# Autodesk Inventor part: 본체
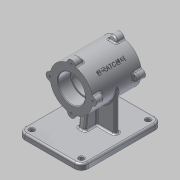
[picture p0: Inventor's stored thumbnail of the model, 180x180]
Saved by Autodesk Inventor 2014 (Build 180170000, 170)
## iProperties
Created: 2015-12
Part Number: 본체
Material: 알루미늄 6061
Document SubType Name: Modeling
Designer: L10
Density: 2.71 g/cm^3
Appearance: 알루미늄 - 평지
Mass: 1154.84 g
Surface Area: 823.447 cm^2
Volume: 426.142 cm^3
Author: L10
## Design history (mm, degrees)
sketch "스케치1"
  geometry: C1 r 37 at (0, 0); 1 further point
  constraints: 1 centre point, 1 coincident
  dimensions: "d0" = 74 diameter of C1
extrude "돌출1" new body sketch "스케치1" stored distance "d1" = 85; taper "d2" = 0 deg
sketch "스케치2"
  geometry: L1 (-42.5, -37)-(-42.5, 37) reference; L2 (-42.5, 37)-(42.5, 37) reference; L3 (42.5, 37)-(42.5, -37) reference; L4 (42.5, -37)-(-42.5, -37) reference; L5 (-42.5, 0)-(-20.5, 0); L6 (-20.5, 0)-(-20.5, 23.5); L7 (-20.5, 23.5)-(-42.5, 23.5); L8 (-42.5, 23.5)-(-42.5, 0); L9 (-20.5, 0)-(20.5, 0); L10 (20.5, 0)-(20.5, 21); L11 (20.5, 21)-(-20.5, 21); L12 (-20.5, 21)-(-20.5, 0); L13 (20.5, 0)-(42.5, 0); L14 (42.5, 0)-(42.5, 23.5); L15 (42.5, 23.5)-(20.5, 23.5); L16 (20.5, 23.5)-(20.5, 0); 2 further points
  constraints: 24 end point, 6 parallel, 3 horizontal, 3 perpendicular, 2 collinear, 1 coincident, 1 midpoint
  dimensions: "d3" = 47 diameter of L7 L9; "d4" = 42 diameter of L11 L9; "d5" = 22 distance of L6.end L7.end; "d6" = 41 distance of L10.end L11.end; "d7" = 85 distance between parallel lines of L14 L8 (derived)
revolve "회전1" sketch "스케치2" stored, may be unused: angle "d8" = 90 deg
node "작업 평면1"
sketch "스케치4"
  geometry: L1 (55, 60)-(-55, 60); L2 (-55, 60)-(-55, -80); L3 (-55, -80)-(55, -80); L4 (55, -80)-(55, 60); L5 (-37, -42.5)-(37, -42.5) reference; 4 further points
  constraints: 8 end point, 2 parallel, 1 horizontal, 1 midpoint, 1 perpendicular, 1 vertical alignment
  dimensions: "d13" = 140 distance of L3.end L1.start; "d14" = 110 distance of L1.start L1.end; "d15" = 37.5 distance between parallel lines of L5 L3
extrude "돌출3" join sketch "스케치4" distance "d16" = 10; taper "d17" = 0 deg
fillet "모깎기1" dims "d18" = 12
hole "구멍1" diameter "d21" = 8; stored, may be unused: countersink angle "d25" = 90 deg, drill point angle "d27" = 118 deg; dims "d19" = 10, "d20" = 10, "d22" = 6, "d23" = 4, "d24" = 2, "d26" = 8
hole "구멍2" diameter "d30" = 8; stored, may be unused: countersink angle "d34" = 90 deg, drill point angle "d36" = 118 deg; dims "d28" = 10, "d29" = 10, "d31" = 6, "d32" = 4, "d33" = 2, "d35" = 8
hole "구멍3" diameter "d39" = 8; stored, may be unused: countersink angle "d43" = 90 deg, drill point angle "d45" = 118 deg; dims "d37" = 10, "d38" = 10, "d40" = 6, "d41" = 4, "d42" = 2, "d44" = 8
hole "구멍4" diameter "d48" = 8; stored, may be unused: countersink angle "d52" = 90 deg, drill point angle "d54" = 118 deg; dims "d46" = 10, "d47" = 10, "d49" = 6, "d50" = 4, "d51" = 2, "d53" = 8
sketch "스케치6"
  geometry: L1 (-55, 48)-(-55, -68) reference; L2 (-43, -80)-(43, -80) reference; L3 (-6, -25)-(6, -25); L4 (6, -25)-(6, 25); L5 (6, 25)-(-6, 25); L6 (-6, 25)-(-6, -25); L7 (-37, -4)-(37, -4); L8 (37, -4)-(37, 4); L9 (37, 4)-(-37, 4); L10 (-37, 4)-(-37, -4); 3 further points
  constraints: 16 end point, 4 parallel, 2 horizontal, 2 midpoint, 2 perpendicular, 1 horizontal alignment, 1 vertical alignment
  dimensions: "d59" = 12 distance of L4.end L5.end; "d60" = 8 distance of L9.end L7.start; "d61" = 76 distance between parallel lines of L2 L7; "d62" = 49 distance between parallel lines of L1 L6; "d63" = 50 distance of L3.end L4.end; "d64" = 74 distance of L8.end L9.end
extrude "돌출4" join sketch "스케치6" stored distance "d65" = 10; taper "d66" = 0 deg
fillet "모깎기2" dims "d67" = 3
chamfer "모따기1" distance "d71" = 1; stored, may be unused: second distance "d72" = 2, angle "d73" = 20 deg
chamfer "모따기2" distance "d74" = 1; stored, may be unused: second distance "d75" = 2, angle "d76" = 20 deg
fillet "모깎기6" dims "d77" = 0.3
feature "면 기울기1" dims angle "d78" = 7 deg
feature "면 기울기2" dims angle "d79" = 7 deg
fillet "모깎기7" dims "d80" = 3
fillet "모깎기8" dims "d81" = 3
fillet "모깎기9" dims "d82" = 3
sketch "스케치9"
  geometry: L1 (-42.5, 31.009)-(-42.5, 44); L2 (-42.5, 44)-(-30.048, 44); L3 (-30.048, 44)-(-25.319, 31.009); L4 (-25.319, 31.009)-(-42.5, 31.009); L5 (-42.5, 37)-(-42.5, -37) reference; L6 (-42.5, 37)-(42.5, 37) reference; 2 further points
  constraints: 8 end point, 3 point on line, 1 parallel, 1 perpendicular, 1 vertical
  dimensions: "d93" = 7 distance of L5.start L1.end; "d94" = 110 deg angle of L3 L6; "d95" = 12.99148 distance of L1.start L1.end; "d126" = 15 distance of L6.start point (-27.5, 37)
extrude "돌출6" join sketch "스케치9" stored distance "d96" = 14; taper "d97" = 0 deg
fillet "모깎기10" dims "d98" = 7
fillet "모깎기11" dims "d99" = 3
hole "구멍5" diameter "d102" = 3.242; stored, may be unused: countersink angle "d106" = 90 deg, drill point angle "d108" = 118 deg; dims "d103" = 9, "d104" = 4, "d105" = 2, "d107" = 11, "d118" = 10, "d119" = 10
sketch "스케치12"
  geometry: L1 (0, 0)-(-26.163, 26.163); L2 (80.055, 0)-(-95.329, 0) reference; A1 r 37 centre (0, 0) between (-9.104, 35.863) and (-35.863, 9.104) reference
  constraints: 2 end point, 1 point on circle
  dimensions: "d120" = 45 deg angle of L1 L2
node "작업 평면3"
sketch "스케치13"
  geometry: L1 (-26.604, 3.602)-(26.604, 3.602); L2 (26.604, 3.602)-(26.604, -3.602); L3 (26.604, -3.602)-(-26.604, -3.602); L4 (-26.604, -3.602)-(-26.604, 3.602); 3 further points
  constraints: 2 midpoint, 1 horizontal alignment, 1 vertical alignment, 2 other
  dimensions: "d121" = 53.2089 distance of L1.start L1.end; "d122" = 7.20489 distance of L1.end L2.end; "d123" = 26.60445 horizontal distance of point (0, 3.602) point (26.604, 0)
feature "엠보싱2" sketch "스케치13" dims "d124" = 0.5, "d125" = 0
node "솔리드1"
pattern_circular "원형 패턴1" dims "d110" = 360 deg
mirror "대칭1"
node "절단 모서리 투영1"
